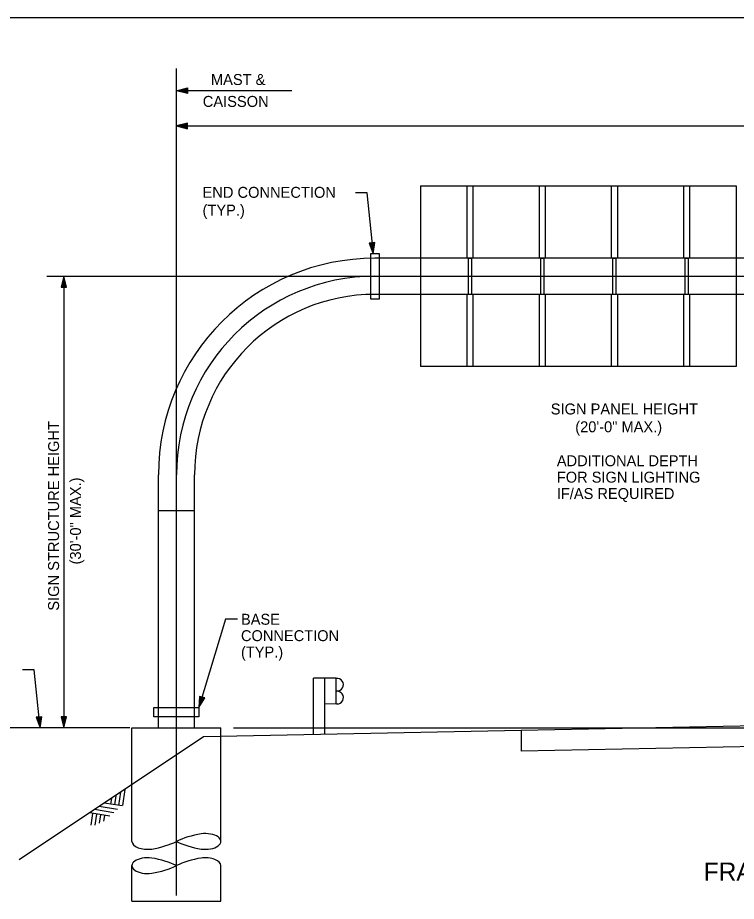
# Model space of a CAD drawing. Extents: x 640117 to 642655, y 297247 to 298435.
# Drawn here: x 641275.4 to 641472.4, y 297584.4 to 297826.5 of the extents above; entities that cross this region are included whole.
import ezdxf

# ---------------------------------------------------------------- set-up
doc = ezdxf.new("R2010")
doc.units = 0
for name, color, linetype in [('10', 7, 'Continuous'), ('2', 7, 'Continuous'), ('25', 7, 'Continuous'), ('46', 7, 'Continuous'), ('47', 7, 'Continuous'), ('49', 7, 'Continuous'), ('50', 7, 'Continuous'), ('51', 7, 'Continuous'), ('52', 7, 'Continuous'), ('53', 7, 'Continuous'), ('55', 7, 'Continuous'), ('56', 7, 'Continuous')]:
    doc.layers.add(name, color=color, linetype=linetype)

msp = doc.modelspace()

# ---------------------------------------------------------------- linework, layer by layer
at = {"layer": '2'}
msp.add_line((640998.46, 297826.46), (641784.46, 297826.46), dxfattribs=at)
at = {"layer": '25'}
for p, q in [((641506.9, 297633.09), (641413.43, 297631.22)), ((641413.43, 297631.22), (641413.43, 297625.53)), ((641506.9, 297627.4), (641413.43, 297625.53))]:
    msp.add_line(p, q, dxfattribs=at)
at = {"layer": '46'}
for p, q in [((641362.69, 297645.53), (641356.51, 297645.53)), ((641356.51, 297630.08), (641356.51, 297645.53)), ((641359.6, 297630.14), (641359.6, 297645.53)), ((641362.69, 297638.5), (641362.69, 297645.53)), ((641363.13, 297638.5), (641359.57, 297638.48))]:
    msp.add_line(p, q, dxfattribs=at)
for centre in [(641362.9, 297643.77), (641362.92, 297640.24)]:
    msp.add_arc(centre, 1.76, 269.5886, 96.9648, dxfattribs=at)
at = {"layer": '47'}
for p, q in [((641326.33, 297629.48), (641275.84, 297595.82)), ((641413.43, 297631.22), (641326.33, 297629.48))]:
    msp.add_line(p, q, dxfattribs=at)
at = {"layer": '49'}
for p, q in [((641385.79, 297780.36), (641385.79, 297760.57)), ((641385.79, 297780.36), (641472.27, 297780.36)), ((641398.52, 297780.36), (641398.52, 297760.57)), ((641400.17, 297780.36), (641400.17, 297760.57)), ((641418.31, 297780.36), (641418.31, 297760.57)), ((641419.96, 297780.36), (641419.96, 297760.57)), ((641438.1, 297780.36), (641438.1, 297760.57)), ((641439.75, 297780.36), (641439.75, 297760.57)), ((641457.89, 297780.36), (641457.89, 297760.57)), ((641459.54, 297780.36), (641459.54, 297760.57)), ((641472.27, 297780.36), (641472.27, 297760.57)), ((641385.79, 297760.57), (641385.79, 297750.68)), ((641472.27, 297760.57), (641472.27, 297750.68)), ((641385.79, 297750.68), (641385.79, 297730.89)), ((641398.52, 297750.68), (641398.52, 297730.89)), ((641400.17, 297750.68), (641400.17, 297730.89)), ((641418.31, 297750.68), (641418.31, 297730.89)), ((641419.96, 297750.68), (641419.96, 297730.89)), ((641438.1, 297750.68), (641438.1, 297730.89)), ((641439.75, 297750.68), (641439.75, 297730.89)), ((641457.89, 297750.68), (641457.89, 297730.89)), ((641459.54, 297750.68), (641459.54, 297730.89)), ((641472.27, 297750.68), (641472.27, 297730.89)), ((641472.27, 297730.89), (641385.79, 297730.89)), ((641313.96, 297691.46), (641323.85, 297691.46))]:
    msp.add_line(p, q, dxfattribs=at)
for points in [[(641398.95, 297760.57), (641399.77, 297760.57), (641399.77, 297750.68), (641398.95, 297750.68)], [(641418.74, 297760.57), (641419.56, 297760.57), (641419.56, 297750.68), (641418.74, 297750.68)], [(641438.53, 297760.57), (641439.35, 297760.57), (641439.35, 297750.68), (641438.53, 297750.68)], [(641458.32, 297760.57), (641459.14, 297760.57), (641459.14, 297750.68), (641458.32, 297750.68)]]:
    msp.add_lwpolyline(points, close=True, dxfattribs=at)
at = {"layer": '50'}
for p, q in [((641318.91, 297773.59), (641318.91, 297812.56)), ((641318.91, 297586.01), (641318.91, 297773.59)), ((641283.4, 297755.63), (641718.24, 297755.63))]:
    msp.add_line(p, q, dxfattribs=at)
msp.add_arc((641373.33, 297701.21), 54.42, 90, 180, dxfattribs=at)
at = {"layer": '51'}
for p, q in [((641306.72, 297631.95), (641331.1, 297631.95)), ((641306.72, 297616.4), (641306.72, 297631.95)), ((641331.1, 297629.57), (641331.1, 297631.95)), ((641331.1, 297600.85), (641331.1, 297629.57)), ((641306.72, 297600.85), (641306.72, 297616.4)), ((641306.72, 297584.45), (641306.72, 297594.22)), ((641331.1, 297584.45), (641331.1, 297594.22)), ((641306.72, 297584.45), (641331.1, 297584.45))]:
    msp.add_line(p, q, dxfattribs=at)
for centre, major_axis, start_param, end_param in [((641331.1, 297594.75), (17.24, 0), 1.89032, 2.356194), ((641326.78, 297600.85), (4.32, 0), 4.455588, 8.110783), ((641311.03, 297600.85), (-4.32, 0), 0, 1.827597), ((641306.72, 297606.94), (-17.24, 0), 1.89032, 2.356194), ((641331.1, 297606.94), (17.24, 0), 3.926991, 4.392865), ((641311.03, 297594.22), (-4.32, 0), 4.455588, 8.110783), ((641306.72, 297588.13), (-17.24, 0), 3.926991, 4.392865), ((641331.1, 297588.13), (17.24, 0), 1.89032, 2.356194), ((641326.78, 297594.22), (4.32, 0), 0, 1.827597), ((641306.72, 297600.32), (-17.24, 0), 1.89032, 2.356194)]:
    msp.add_ellipse(centre, major_axis=major_axis, ratio=0.5, start_param=start_param, end_param=end_param, dxfattribs=at)
at = {"layer": '52'}
for p, q in [((641350.53, 297806.45), (641318.91, 297806.45)), ((641321.91, 297797.54), (641318.91, 297796.79)), ((641318.91, 297796.79), (641321.91, 297796.04)), ((641318.91, 297796.79), (641694.88, 297796.79)), ((641321.73, 297797.31), (641319.64, 297796.79)), ((641319.64, 297796.79), (641321.73, 297796.27)), ((641321.55, 297797.08), (641320.37, 297796.79)), ((641320.37, 297796.79), (641321.55, 297796.49)), ((641321.48, 297796.88), (641321.11, 297796.79)), ((641321.11, 297796.79), (641321.46, 297796.7)), ((641321.55, 297796.49), (641321.55, 297797.08)), ((641321.73, 297796.27), (641321.73, 297797.31)), ((641321.91, 297796.04), (641321.91, 297797.54)), ((641373.25, 297764.87), (641371.76, 297764.72)), ((641371.76, 297764.72), (641372.81, 297761.81)), ((641373.05, 297764.67), (641372.01, 297764.57)), ((641372.01, 297764.57), (641372.74, 297762.54)), ((641372.74, 297762.54), (641373.05, 297764.67)), ((641372.81, 297761.81), (641373.25, 297764.87)), ((641372.84, 297764.47), (641372.25, 297764.41)), ((641372.25, 297764.41), (641372.66, 297763.27)), ((641372.46, 297764.36), (641372.59, 297764)), ((641372.59, 297764), (641372.64, 297764.36)), ((641372.66, 297763.27), (641372.84, 297764.47)), ((641288.03, 297755.63), (641287.28, 297752.63)), ((641288.03, 297754.89), (641287.51, 297752.8)), ((641288.78, 297752.63), (641288.03, 297755.63)), ((641288.03, 297755.63), (641288.03, 297631.95)), ((641288.55, 297752.8), (641288.03, 297754.89)), ((641287.28, 297752.63), (641288.78, 297752.63)), ((641287.51, 297752.8), (641288.55, 297752.8)), ((641288.03, 297754.16), (641287.73, 297752.98)), ((641287.73, 297752.98), (641288.32, 297752.98)), ((641288.03, 297753.43), (641287.94, 297753.07)), ((641288.32, 297752.98), (641288.03, 297754.16)), ((641288.12, 297753.05), (641288.03, 297753.43)), ((641332.34, 297661.74), (641325.09, 297637.49)), ((641335.62, 297661.74), (641332.34, 297661.74)), ((641325.23, 297640.58), (641325.09, 297637.49)), ((641325.09, 297637.49), (641326.67, 297640.15)), ((641326.67, 297640.15), (641325.23, 297640.58)), ((641325.4, 297640.34), (641325.3, 297638.19)), ((641325.3, 297638.19), (641326.4, 297640.04)), ((641326.4, 297640.04), (641325.4, 297640.34)), ((641325.57, 297640.11), (641325.51, 297638.89)), ((641325.51, 297638.89), (641326.13, 297639.94)), ((641326.13, 297639.94), (641325.57, 297640.11)), ((641325.74, 297639.98), (641325.72, 297639.59)), ((641325.72, 297639.59), (641325.91, 297639.91)), ((641282, 297635.01), (641280.51, 297634.86)), ((641280.51, 297634.86), (641281.56, 297631.95)), ((641281.8, 297634.81), (641280.76, 297634.71)), ((641280.76, 297634.71), (641281.49, 297632.68)), ((641281.59, 297634.61), (641281, 297634.55)), ((641281, 297634.55), (641281.41, 297633.41)), ((641281.21, 297634.5), (641281.34, 297634.14)), ((641281.34, 297634.14), (641281.39, 297634.5)), ((641281.41, 297633.41), (641281.59, 297634.61)), ((641281.49, 297632.68), (641281.8, 297634.81)), ((641281.56, 297631.95), (641282, 297635.01)), ((641287.28, 297634.95), (641288.03, 297631.95)), ((641288.78, 297634.95), (641287.28, 297634.95)), ((641287.51, 297634.77), (641288.03, 297632.68)), ((641288.55, 297634.77), (641287.51, 297634.77)), ((641287.73, 297634.6), (641288.03, 297633.42)), ((641288.32, 297634.6), (641287.73, 297634.6)), ((641287.94, 297634.53), (641288.03, 297634.15)), ((641288.03, 297631.95), (641288.78, 297634.95)), ((641288.03, 297632.68), (641288.55, 297634.77)), ((641288.03, 297633.42), (641288.32, 297634.6)), ((641288.03, 297634.15), (641288.12, 297634.51)), ((641306.16, 297631.95), (641272.14, 297631.95)), ((641334.59, 297631.95), (641729.96, 297631.95))]:
    msp.add_line(p, q, dxfattribs=at)
for points in [[(641372.83, 297762.56), (641371.22, 297778.46), (641367.98, 297778.46)], [(641281.56, 297631.95), (641279.95, 297647.85), (641276.71, 297647.85)]]:
    msp.add_lwpolyline(points, dxfattribs=at)
at = {"layer": '53'}
for p, q in [((641318.91, 297806.45), (641321.91, 297807.2)), ((641321.91, 297805.7), (641318.91, 297806.45)), ((641319.64, 297806.45), (641321.73, 297806.97)), ((641321.73, 297805.93), (641319.64, 297806.45)), ((641320.37, 297806.45), (641321.55, 297806.74)), ((641321.55, 297806.15), (641320.37, 297806.45)), ((641321.11, 297806.45), (641321.46, 297806.54)), ((641321.48, 297806.36), (641321.11, 297806.45)), ((641321.55, 297806.74), (641321.55, 297806.15)), ((641321.73, 297806.97), (641321.73, 297805.93)), ((641321.91, 297807.2), (641321.91, 297805.7))]:
    msp.add_line(p, q, dxfattribs=at)
at = {"layer": '55'}
for p, q in [((641506.9, 297760.57), (641373.33, 297760.57)), ((641506.9, 297750.68), (641373.33, 297750.68)), ((641313.96, 297631.95), (641313.96, 297701.21)), ((641323.85, 297631.95), (641323.85, 297701.21))]:
    msp.add_line(p, q, dxfattribs=at)
for points in [[(641374.56, 297761.81), (641372.09, 297761.81), (641372.09, 297749.44), (641374.56, 297749.44)], [(641325.09, 297637.49), (641325.09, 297635.01), (641312.72, 297635.01), (641312.72, 297637.49)]]:
    msp.add_lwpolyline(points, close=True, dxfattribs=at)
for radius in [59.36, 49.47]:
    msp.add_arc((641373.33, 297701.21), radius, 90, 180, dxfattribs=at)
at = {"layer": '56'}
for p, q in [((641304.2, 297610.72), (641304.9, 297615.09)), ((641300.91, 297611.06), (641301.17, 297612.64)), ((641301.99, 297610.89), (641302.39, 297613.31)), ((641303.08, 297610.71), (641303.67, 297614.33)), ((641302.8, 297609.64), (641297.77, 297610.46)), ((641304.01, 297610.56), (641299.14, 297611.35)), ((641300.63, 297607.77), (641295.2, 297608.65)), ((641295.52, 297605.28), (641296.04, 297608.51)), ((641301.77, 297608.7), (641296.41, 297609.56)), ((641296.64, 297605.28), (641297.13, 297608.34)), ((641297.84, 297605.87), (641298.21, 297608.16)), ((641299.04, 297606.36), (641299.3, 297607.99))]:
    msp.add_line(p, q, dxfattribs=at)

# ---------------------------------------------------------------- texts
at = {"layer": '10'}
for s, height, p in [('ADDITIONAL DEPTH', 2.9917, (641423.17, 297703.61)), ('FOR SIGN LIGHTING', 2.9917, (641423.17, 297699.12)), ('IF/AS REQUIRED', 2.9917, (641423.17, 297694.63)), ('BASE', 2.992, (641336.6, 297660.2)), ('CONNECTION ', 2.9917, (641336.6, 297655.71)), ('(TYP.)', 2.992, (641336.6, 297651.22))]:
    msp.add_text(s, height=height, dxfattribs=at).set_placement(p)
at = {"layer": '2'}
for s, p in [('SIGN PANEL HEIGHT', (641421.5, 297717.79)), ('(20\'-0" MAX.)', (641428.21, 297712.91))]:
    msp.add_text(s, height=3, dxfattribs=at).set_placement(p)
for s, p in [('SIGN STRUCTURE HEIGHT', (641286.74, 297664.05)), ('(30\'-0" MAX.)', (641292.74, 297676.71))]:
    msp.add_text(s, height=3, rotation=90, dxfattribs=at).set_placement(p)
at = {"layer": '53'}
for s, height, p in [('  MAST &', 3, (641326.13, 297808.02)), ('CAISSON', 3, (641326.13, 297802.02)), ('END CONNECTION', 3, (641326.06, 297777.12)), ('(TYP.)', 3, (641326.06, 297772.25)), ('FRAME STRUCTURE', 5, (641463.45, 297590.08))]:
    msp.add_text(s, height=height, dxfattribs=at).set_placement(p)

doc.saveas('drawing.dxf')
